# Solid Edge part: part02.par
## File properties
Author: CADCIM
Template: Iso Part.par
Last saved by: Cadcim
Revision: 6
Application: Solid Edge
Accuracy: 0.990
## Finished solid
Body 1: solid body, 25 faces, 64 edges, 38 vertices.
  Faces by surface: plane 14, cylinder 11
  Edges by curve: line 42, circle 20, ellipse 2
Bounding box of the edges (mm): 45.000 x 35.000 x 22.324, from (-22.5, -17.5, 0) to (22.5, 17.5, 22.3241).
Cylindrical faces by radius (mm): R2 x4, R2.5 x3, R3.75 x1, R5 x2, R7.5 x1
Planar faces by outward normal: +x 1, +y 2, +z 3, -x 4, -y 2, -z 1, oblique 1
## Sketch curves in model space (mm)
arc centre (10.4792, 0, 17.0208) radius 7.5 from (10.4792, 7.5, 17.0208) through (5.1782, -0.2222, 22.3218) to (10.4792, -7.5, 17.0208)
line (10.4792, 7.5, 17.0208) -> (22.5, 7.5, 5)
line (22.5, 7.5, 5) -> (22.5, -7.5, 5)
line (22.5, -7.5, 5) -> (10.4792, -7.5, 17.0208)
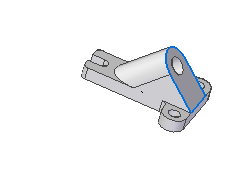
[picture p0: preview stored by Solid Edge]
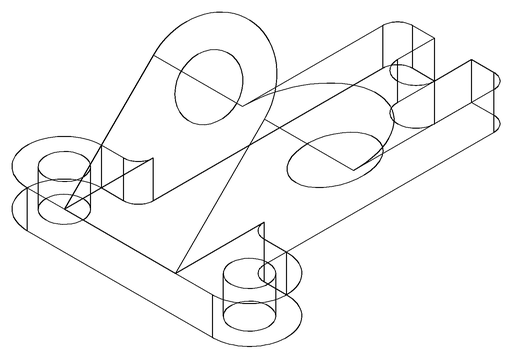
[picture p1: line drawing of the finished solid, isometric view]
